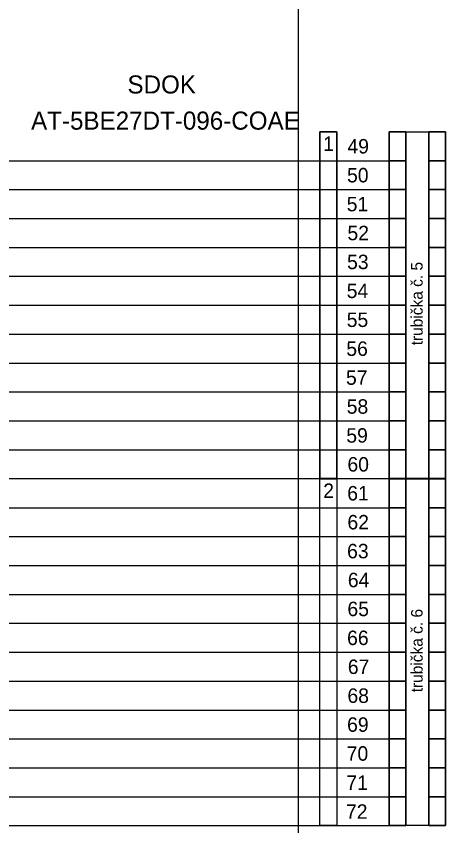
# Model space of a CAD drawing. Extents: x 1901 to 2519, y -3585 to -3154.
# Drawn here: x 1980.5 to 2032.8, y -3478.9 to -3380.3 of the extents above; entities that cross this region are included whole.
import ezdxf

# ---------------------------------------------------------------- set-up
doc = ezdxf.new("R2010")
doc.units = 0
doc.layers.add('rozvláknění', color=7, linetype='Continuous')
doc.layers.add('Vrstva 11', color=7, linetype='Continuous')

msp = doc.modelspace()

# ---------------------------------------------------------------- linework, layer by layer
at = {"layer": 'rozvláknění'}
for p, q in [((1933.193, -3397.902), (2025.898, -3397.904)), ((1933.193, -3401.42), (2025.898, -3401.423)), ((1933.193, -3404.939), (2025.898, -3404.941)), ((1933.193, -3408.457), (2025.898, -3408.459)), ((1933.193, -3411.975), (2025.898, -3411.977)), ((1933.193, -3415.493), (2025.898, -3415.495)), ((1933.193, -3419.011), (2025.898, -3419.014)), ((1933.193, -3422.53), (2025.898, -3422.532)), ((1933.193, -3426.048), (2025.898, -3426.05)), ((1933.193, -3429.566), (2025.898, -3429.568)), ((1933.193, -3433.084), (2025.898, -3433.086)), ((1933.193, -3436.602), (2025.898, -3436.605)), ((1933.193, -3440.142), (2025.898, -3440.144)), ((1933.193, -3443.66), (2025.898, -3443.663)), ((1933.193, -3447.179), (2025.898, -3447.181)), ((1933.193, -3450.697), (2025.898, -3450.699)), ((1933.193, -3454.215), (2025.898, -3454.217)), ((1933.193, -3457.733), (2025.898, -3457.735)), ((1933.193, -3461.251), (2025.898, -3461.254)), ((1933.193, -3464.77), (2025.898, -3464.772)), ((1933.193, -3468.288), (2025.898, -3468.29)), ((1933.193, -3471.806), (2025.898, -3471.808)), ((1933.193, -3475.324), (2025.898, -3475.326)), ((1933.193, -3478.842), (2025.898, -3478.845))]:
    msp.add_line(p, q, dxfattribs=at)
for points in [[(2014.869, -3178.545), (2059.522, -3178.544), (2059.522, -3570.656), (2014.869, -3570.656)], [(2019.518, -3436.605), (2017.476, -3436.605), (2017.476, -3394.386), (2019.518, -3394.386)], [(2025.898, -3394.386), (2027.939, -3394.386), (2027.939, -3397.904), (2025.898, -3397.904)], [(2025.898, -3394.386), (2027.939, -3394.386), (2027.939, -3397.904), (2025.898, -3397.904)], [(2027.939, -3394.386), (2030.726, -3394.386), (2030.726, -3436.601), (2027.939, -3436.601)], [(2030.726, -3394.386), (2032.767, -3394.386), (2032.767, -3397.904), (2030.726, -3397.904)], [(2030.726, -3394.386), (2032.767, -3394.386), (2032.767, -3397.904), (2030.726, -3397.904)], [(2025.898, -3397.904), (2027.939, -3397.904), (2027.939, -3401.423), (2025.898, -3401.423)], [(2025.898, -3397.904), (2027.939, -3397.904), (2027.939, -3401.423), (2025.898, -3401.423)], [(2030.726, -3397.904), (2032.767, -3397.904), (2032.767, -3401.423), (2030.726, -3401.423)], [(2030.726, -3397.904), (2032.767, -3397.904), (2032.767, -3401.423), (2030.726, -3401.423)], [(2025.898, -3401.423), (2027.939, -3401.423), (2027.939, -3404.941), (2025.898, -3404.941)], [(2025.898, -3401.423), (2027.939, -3401.423), (2027.939, -3404.941), (2025.898, -3404.941)], [(2030.726, -3401.423), (2032.767, -3401.423), (2032.767, -3404.941), (2030.726, -3404.941)], [(2030.726, -3401.423), (2032.767, -3401.423), (2032.767, -3404.941), (2030.726, -3404.941)], [(2025.898, -3404.941), (2027.939, -3404.941), (2027.939, -3408.459), (2025.898, -3408.459)], [(2025.898, -3404.941), (2027.939, -3404.941), (2027.939, -3408.459), (2025.898, -3408.459)], [(2030.726, -3404.941), (2032.767, -3404.941), (2032.767, -3408.459), (2030.726, -3408.459)], [(2030.726, -3404.941), (2032.767, -3404.941), (2032.767, -3408.459), (2030.726, -3408.459)], [(2025.898, -3408.459), (2027.939, -3408.459), (2027.939, -3411.977), (2025.898, -3411.977)], [(2025.898, -3408.459), (2027.939, -3408.459), (2027.939, -3411.977), (2025.898, -3411.977)], [(2030.726, -3408.459), (2032.767, -3408.459), (2032.767, -3411.977), (2030.726, -3411.977)], [(2030.726, -3408.459), (2032.767, -3408.459), (2032.767, -3411.977), (2030.726, -3411.977)], [(2025.898, -3411.977), (2027.939, -3411.977), (2027.939, -3415.495), (2025.898, -3415.495)], [(2025.898, -3411.977), (2027.939, -3411.977), (2027.939, -3415.495), (2025.898, -3415.495)], [(2030.726, -3411.977), (2032.767, -3411.977), (2032.767, -3415.495), (2030.726, -3415.495)], [(2030.726, -3411.977), (2032.767, -3411.977), (2032.767, -3415.495), (2030.726, -3415.495)], [(2025.898, -3415.495), (2027.939, -3415.495), (2027.939, -3419.014), (2025.898, -3419.014)], [(2025.898, -3415.495), (2027.939, -3415.495), (2027.939, -3419.014), (2025.898, -3419.014)], [(2030.726, -3415.495), (2032.767, -3415.495), (2032.767, -3419.014), (2030.726, -3419.014)], [(2030.726, -3415.495), (2032.767, -3415.495), (2032.767, -3419.014), (2030.726, -3419.014)], [(2025.898, -3419.014), (2027.939, -3419.014), (2027.939, -3422.532), (2025.898, -3422.532)], [(2025.898, -3419.014), (2027.939, -3419.014), (2027.939, -3422.532), (2025.898, -3422.532)], [(2030.726, -3419.014), (2032.767, -3419.014), (2032.767, -3422.532), (2030.726, -3422.532)], [(2030.726, -3419.014), (2032.767, -3419.014), (2032.767, -3422.532), (2030.726, -3422.532)], [(2025.898, -3422.532), (2027.939, -3422.532), (2027.939, -3426.05), (2025.898, -3426.05)], [(2025.898, -3422.532), (2027.939, -3422.532), (2027.939, -3426.05), (2025.898, -3426.05)], [(2030.726, -3422.532), (2032.767, -3422.532), (2032.767, -3426.05), (2030.726, -3426.05)], [(2030.726, -3422.532), (2032.767, -3422.532), (2032.767, -3426.05), (2030.726, -3426.05)], [(2025.898, -3426.05), (2027.939, -3426.05), (2027.939, -3429.568), (2025.898, -3429.568)], [(2025.898, -3426.05), (2027.939, -3426.05), (2027.939, -3429.568), (2025.898, -3429.568)], [(2030.726, -3426.05), (2032.767, -3426.05), (2032.767, -3429.568), (2030.726, -3429.568)], [(2030.726, -3426.05), (2032.767, -3426.05), (2032.767, -3429.568), (2030.726, -3429.568)], [(2025.898, -3429.568), (2027.939, -3429.568), (2027.939, -3433.086), (2025.898, -3433.086)], [(2025.898, -3429.568), (2027.939, -3429.568), (2027.939, -3433.086), (2025.898, -3433.086)], [(2030.726, -3429.568), (2032.767, -3429.568), (2032.767, -3433.086), (2030.726, -3433.086)], [(2030.726, -3429.568), (2032.767, -3429.568), (2032.767, -3433.086), (2030.726, -3433.086)], [(2025.898, -3433.086), (2027.939, -3433.086), (2027.939, -3436.605), (2025.898, -3436.605)], [(2025.898, -3433.086), (2027.939, -3433.086), (2027.939, -3436.605), (2025.898, -3436.605)], [(2030.726, -3433.086), (2032.767, -3433.086), (2032.767, -3436.605), (2030.726, -3436.605)], [(2030.726, -3433.086), (2032.767, -3433.086), (2032.767, -3436.605), (2030.726, -3436.605)], [(2019.518, -3478.845), (2017.476, -3478.845), (2017.476, -3436.626), (2019.518, -3436.626)], [(2025.898, -3436.626), (2027.939, -3436.626), (2027.939, -3440.144), (2025.898, -3440.144)], [(2025.898, -3436.626), (2027.939, -3436.626), (2027.939, -3440.144), (2025.898, -3440.144)], [(2027.939, -3436.626), (2030.726, -3436.626), (2030.726, -3478.841), (2027.939, -3478.841)], [(2030.726, -3436.626), (2032.767, -3436.626), (2032.767, -3440.144), (2030.726, -3440.144)], [(2030.726, -3436.626), (2032.767, -3436.626), (2032.767, -3440.144), (2030.726, -3440.144)], [(2025.898, -3440.144), (2027.939, -3440.144), (2027.939, -3443.663), (2025.898, -3443.663)], [(2025.898, -3440.144), (2027.939, -3440.144), (2027.939, -3443.663), (2025.898, -3443.663)], [(2030.726, -3440.144), (2032.767, -3440.144), (2032.767, -3443.663), (2030.726, -3443.663)], [(2030.726, -3440.144), (2032.767, -3440.144), (2032.767, -3443.663), (2030.726, -3443.663)], [(2025.898, -3443.663), (2027.939, -3443.663), (2027.939, -3447.181), (2025.898, -3447.181)], [(2025.898, -3443.663), (2027.939, -3443.663), (2027.939, -3447.181), (2025.898, -3447.181)], [(2030.726, -3443.663), (2032.767, -3443.663), (2032.767, -3447.181), (2030.726, -3447.181)], [(2030.726, -3443.663), (2032.767, -3443.663), (2032.767, -3447.181), (2030.726, -3447.181)], [(2025.898, -3447.181), (2027.939, -3447.181), (2027.939, -3450.699), (2025.898, -3450.699)], [(2025.898, -3447.181), (2027.939, -3447.181), (2027.939, -3450.699), (2025.898, -3450.699)], [(2030.726, -3447.181), (2032.767, -3447.181), (2032.767, -3450.699), (2030.726, -3450.699)], [(2030.726, -3447.181), (2032.767, -3447.181), (2032.767, -3450.699), (2030.726, -3450.699)], [(2025.898, -3450.699), (2027.939, -3450.699), (2027.939, -3454.217), (2025.898, -3454.217)], [(2025.898, -3450.699), (2027.939, -3450.699), (2027.939, -3454.217), (2025.898, -3454.217)], [(2030.726, -3450.699), (2032.767, -3450.699), (2032.767, -3454.217), (2030.726, -3454.217)], [(2030.726, -3450.699), (2032.767, -3450.699), (2032.767, -3454.217), (2030.726, -3454.217)], [(2025.898, -3454.217), (2027.939, -3454.217), (2027.939, -3457.735), (2025.898, -3457.735)], [(2025.898, -3454.217), (2027.939, -3454.217), (2027.939, -3457.735), (2025.898, -3457.735)], [(2030.726, -3454.217), (2032.767, -3454.217), (2032.767, -3457.735), (2030.726, -3457.735)], [(2030.726, -3454.217), (2032.767, -3454.217), (2032.767, -3457.735), (2030.726, -3457.735)], [(2025.898, -3457.735), (2027.939, -3457.735), (2027.939, -3461.254), (2025.898, -3461.254)], [(2025.898, -3457.735), (2027.939, -3457.735), (2027.939, -3461.254), (2025.898, -3461.254)], [(2030.726, -3457.735), (2032.767, -3457.735), (2032.767, -3461.254), (2030.726, -3461.254)], [(2030.726, -3457.735), (2032.767, -3457.735), (2032.767, -3461.254), (2030.726, -3461.254)], [(2025.898, -3461.254), (2027.939, -3461.254), (2027.939, -3464.772), (2025.898, -3464.772)], [(2025.898, -3461.254), (2027.939, -3461.254), (2027.939, -3464.772), (2025.898, -3464.772)], [(2030.726, -3461.254), (2032.767, -3461.254), (2032.767, -3464.772), (2030.726, -3464.772)], [(2030.726, -3461.254), (2032.767, -3461.254), (2032.767, -3464.772), (2030.726, -3464.772)], [(2025.898, -3464.772), (2027.939, -3464.772), (2027.939, -3468.29), (2025.898, -3468.29)], [(2025.898, -3464.772), (2027.939, -3464.772), (2027.939, -3468.29), (2025.898, -3468.29)], [(2030.726, -3464.772), (2032.767, -3464.772), (2032.767, -3468.29), (2030.726, -3468.29)], [(2030.726, -3464.772), (2032.767, -3464.772), (2032.767, -3468.29), (2030.726, -3468.29)], [(2025.898, -3468.29), (2027.939, -3468.29), (2027.939, -3471.808), (2025.898, -3471.808)], [(2025.898, -3468.29), (2027.939, -3468.29), (2027.939, -3471.808), (2025.898, -3471.808)], [(2030.726, -3468.29), (2032.767, -3468.29), (2032.767, -3471.808), (2030.726, -3471.808)], [(2030.726, -3468.29), (2032.767, -3468.29), (2032.767, -3471.808), (2030.726, -3471.808)], [(2025.898, -3471.808), (2027.939, -3471.808), (2027.939, -3475.326), (2025.898, -3475.326)], [(2025.898, -3471.808), (2027.939, -3471.808), (2027.939, -3475.326), (2025.898, -3475.326)], [(2030.726, -3471.808), (2032.767, -3471.808), (2032.767, -3475.326), (2030.726, -3475.326)], [(2030.726, -3471.808), (2032.767, -3471.808), (2032.767, -3475.326), (2030.726, -3475.326)], [(2025.898, -3475.326), (2027.939, -3475.326), (2027.939, -3478.845), (2025.898, -3478.845)], [(2025.898, -3475.326), (2027.939, -3475.326), (2027.939, -3478.845), (2025.898, -3478.845)], [(2030.726, -3475.326), (2032.767, -3475.326), (2032.767, -3478.845), (2030.726, -3478.845)], [(2030.726, -3475.326), (2032.767, -3475.326), (2032.767, -3478.845), (2030.726, -3478.845)]]:
    msp.add_lwpolyline(points, close=True, dxfattribs=at)
for points in [[(2019.518, -3394.386), (2017.476, -3394.386), (2017.476, -3436.605), (2019.518, -3436.605), (2019.518, -3394.386)], [(2025.898, -3397.904), (2027.939, -3397.904), (2027.939, -3394.386), (2025.898, -3394.386), (2025.898, -3397.904)], [(2030.726, -3397.904), (2032.767, -3397.904), (2032.767, -3394.386), (2030.726, -3394.386), (2030.726, -3397.904)], [(2025.898, -3401.423), (2027.939, -3401.423), (2027.939, -3397.904), (2025.898, -3397.904), (2025.898, -3401.423)], [(2030.726, -3401.423), (2032.767, -3401.423), (2032.767, -3397.904), (2030.726, -3397.904), (2030.726, -3401.423)], [(2025.898, -3404.941), (2027.939, -3404.941), (2027.939, -3401.423), (2025.898, -3401.423), (2025.898, -3404.941)], [(2030.726, -3404.941), (2032.767, -3404.941), (2032.767, -3401.423), (2030.726, -3401.423), (2030.726, -3404.941)], [(2025.898, -3408.459), (2027.939, -3408.459), (2027.939, -3404.941), (2025.898, -3404.941), (2025.898, -3408.459)], [(2030.726, -3408.459), (2032.767, -3408.459), (2032.767, -3404.941), (2030.726, -3404.941), (2030.726, -3408.459)], [(2025.898, -3411.977), (2027.939, -3411.977), (2027.939, -3408.459), (2025.898, -3408.459), (2025.898, -3411.977)], [(2030.726, -3411.977), (2032.767, -3411.977), (2032.767, -3408.459), (2030.726, -3408.459), (2030.726, -3411.977)], [(2025.898, -3415.495), (2027.939, -3415.495), (2027.939, -3411.977), (2025.898, -3411.977), (2025.898, -3415.495)], [(2030.726, -3415.495), (2032.767, -3415.495), (2032.767, -3411.977), (2030.726, -3411.977), (2030.726, -3415.495)], [(2025.898, -3419.014), (2027.939, -3419.014), (2027.939, -3415.495), (2025.898, -3415.495), (2025.898, -3419.014)], [(2030.726, -3419.014), (2032.767, -3419.014), (2032.767, -3415.495), (2030.726, -3415.495), (2030.726, -3419.014)], [(2025.898, -3422.532), (2027.939, -3422.532), (2027.939, -3419.014), (2025.898, -3419.014), (2025.898, -3422.532)], [(2030.726, -3422.532), (2032.767, -3422.532), (2032.767, -3419.014), (2030.726, -3419.014), (2030.726, -3422.532)], [(2025.898, -3426.05), (2027.939, -3426.05), (2027.939, -3422.532), (2025.898, -3422.532), (2025.898, -3426.05)], [(2030.726, -3426.05), (2032.767, -3426.05), (2032.767, -3422.532), (2030.726, -3422.532), (2030.726, -3426.05)], [(2025.898, -3429.568), (2027.939, -3429.568), (2027.939, -3426.05), (2025.898, -3426.05), (2025.898, -3429.568)], [(2030.726, -3429.568), (2032.767, -3429.568), (2032.767, -3426.05), (2030.726, -3426.05), (2030.726, -3429.568)], [(2025.898, -3433.086), (2027.939, -3433.086), (2027.939, -3429.568), (2025.898, -3429.568), (2025.898, -3433.086)], [(2030.726, -3433.086), (2032.767, -3433.086), (2032.767, -3429.568), (2030.726, -3429.568), (2030.726, -3433.086)], [(2025.898, -3436.605), (2027.939, -3436.605), (2027.939, -3433.086), (2025.898, -3433.086), (2025.898, -3436.605)], [(2030.726, -3436.605), (2032.767, -3436.605), (2032.767, -3433.086), (2030.726, -3433.086), (2030.726, -3436.605)], [(2025.898, -3440.144), (2027.939, -3440.144), (2027.939, -3436.626), (2025.898, -3436.626), (2025.898, -3440.144)], [(2030.726, -3440.144), (2032.767, -3440.144), (2032.767, -3436.626), (2030.726, -3436.626), (2030.726, -3440.144)], [(2025.898, -3443.663), (2027.939, -3443.663), (2027.939, -3440.144), (2025.898, -3440.144), (2025.898, -3443.663)], [(2030.726, -3443.663), (2032.767, -3443.663), (2032.767, -3440.144), (2030.726, -3440.144), (2030.726, -3443.663)], [(2025.898, -3447.181), (2027.939, -3447.181), (2027.939, -3443.663), (2025.898, -3443.663), (2025.898, -3447.181)], [(2030.726, -3447.181), (2032.767, -3447.181), (2032.767, -3443.663), (2030.726, -3443.663), (2030.726, -3447.181)], [(2025.898, -3450.699), (2027.939, -3450.699), (2027.939, -3447.181), (2025.898, -3447.181), (2025.898, -3450.699)], [(2030.726, -3450.699), (2032.767, -3450.699), (2032.767, -3447.181), (2030.726, -3447.181), (2030.726, -3450.699)], [(2025.898, -3454.217), (2027.939, -3454.217), (2027.939, -3450.699), (2025.898, -3450.699), (2025.898, -3454.217)], [(2030.726, -3454.217), (2032.767, -3454.217), (2032.767, -3450.699), (2030.726, -3450.699), (2030.726, -3454.217)], [(2025.898, -3457.735), (2027.939, -3457.735), (2027.939, -3454.217), (2025.898, -3454.217), (2025.898, -3457.735)], [(2030.726, -3457.735), (2032.767, -3457.735), (2032.767, -3454.217), (2030.726, -3454.217), (2030.726, -3457.735)], [(2025.898, -3461.254), (2027.939, -3461.254), (2027.939, -3457.735), (2025.898, -3457.735), (2025.898, -3461.254)], [(2030.726, -3461.254), (2032.767, -3461.254), (2032.767, -3457.735), (2030.726, -3457.735), (2030.726, -3461.254)], [(2025.898, -3464.772), (2027.939, -3464.772), (2027.939, -3461.254), (2025.898, -3461.254), (2025.898, -3464.772)], [(2030.726, -3464.772), (2032.767, -3464.772), (2032.767, -3461.254), (2030.726, -3461.254), (2030.726, -3464.772)], [(2025.898, -3468.29), (2027.939, -3468.29), (2027.939, -3464.772), (2025.898, -3464.772), (2025.898, -3468.29)], [(2030.726, -3468.29), (2032.767, -3468.29), (2032.767, -3464.772), (2030.726, -3464.772), (2030.726, -3468.29)], [(2025.898, -3471.808), (2027.939, -3471.808), (2027.939, -3468.29), (2025.898, -3468.29), (2025.898, -3471.808)], [(2030.726, -3471.808), (2032.767, -3471.808), (2032.767, -3468.29), (2030.726, -3468.29), (2030.726, -3471.808)], [(2025.898, -3475.326), (2027.939, -3475.326), (2027.939, -3471.808), (2025.898, -3471.808), (2025.898, -3475.326)], [(2030.726, -3475.326), (2032.767, -3475.326), (2032.767, -3471.808), (2030.726, -3471.808), (2030.726, -3475.326)], [(2025.898, -3478.845), (2027.939, -3478.845), (2027.939, -3475.326), (2025.898, -3475.326), (2025.898, -3478.845)], [(2030.726, -3478.845), (2032.767, -3478.845), (2032.767, -3475.326), (2030.726, -3475.326), (2030.726, -3478.845)]]:
    msp.add_lwpolyline(points, dxfattribs=at)

# ---------------------------------------------------------------- texts
for s, p in [('1', (2017.875, -3396.712)), ('49', (2020.825, -3397.022)), ('50', (2020.778, -3400.542)), ('51', (2020.736, -3404.062)), ('52', (2020.825, -3407.582)), ('53', (2020.778, -3411.102)), ('54', (2020.736, -3414.622)), ('55', (2020.736, -3418.142)), ('56', (2020.689, -3421.662)), ('57', (2020.647, -3425.182)), ('58', (2020.736, -3428.702)), ('59', (2020.689, -3432.222)), ('60', (2020.825, -3435.742)), ('2', (2017.875, -3438.952)), ('61', (2020.801, -3439.262)), ('62', (2020.825, -3442.782)), ('63', (2020.783, -3446.302)), ('64', (2020.872, -3449.822)), ('65', (2020.825, -3453.342)), ('66', (2020.783, -3456.862)), ('67', (2020.872, -3460.382)), ('68', (2020.825, -3463.902)), ('69', (2020.783, -3467.422)), ('70', (2020.736, -3470.942)), ('71', (2020.689, -3474.491)), ('72', (2020.647, -3478.011))]:
    msp.add_text(s, height=1.76, dxfattribs=at).set_placement(p)
for s, p in [('trubička č. 5', (2029.973, -3420.375)), ('trubička č. 6', (2029.973, -3462.615))]:
    msp.add_text(s, height=1.408, rotation=90, dxfattribs=at).set_placement(p)
at = {"layer": 'Vrstva 11'}
for s, p in [('SDOK', (1994.056, -3389.721)), ('AT-5BE27DT-096-COAE', (1982.325, -3394.121))]:
    msp.add_text(s, height=2.2, dxfattribs=at).set_placement(p)

doc.saveas('drawing.dxf')
